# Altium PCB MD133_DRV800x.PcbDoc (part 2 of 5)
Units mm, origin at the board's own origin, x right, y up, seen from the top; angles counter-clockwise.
Board outline 152.66 x 101.89 mm, 4 copper layers (Top Layer, Mid-Layer 1, Mid-Layer 2, Bottom Layer), stack 2.355 mm thick; 306 components, 166 nets, 1010 pads, 1623 vias.
Unrouted connection lines stored in the file: 4.
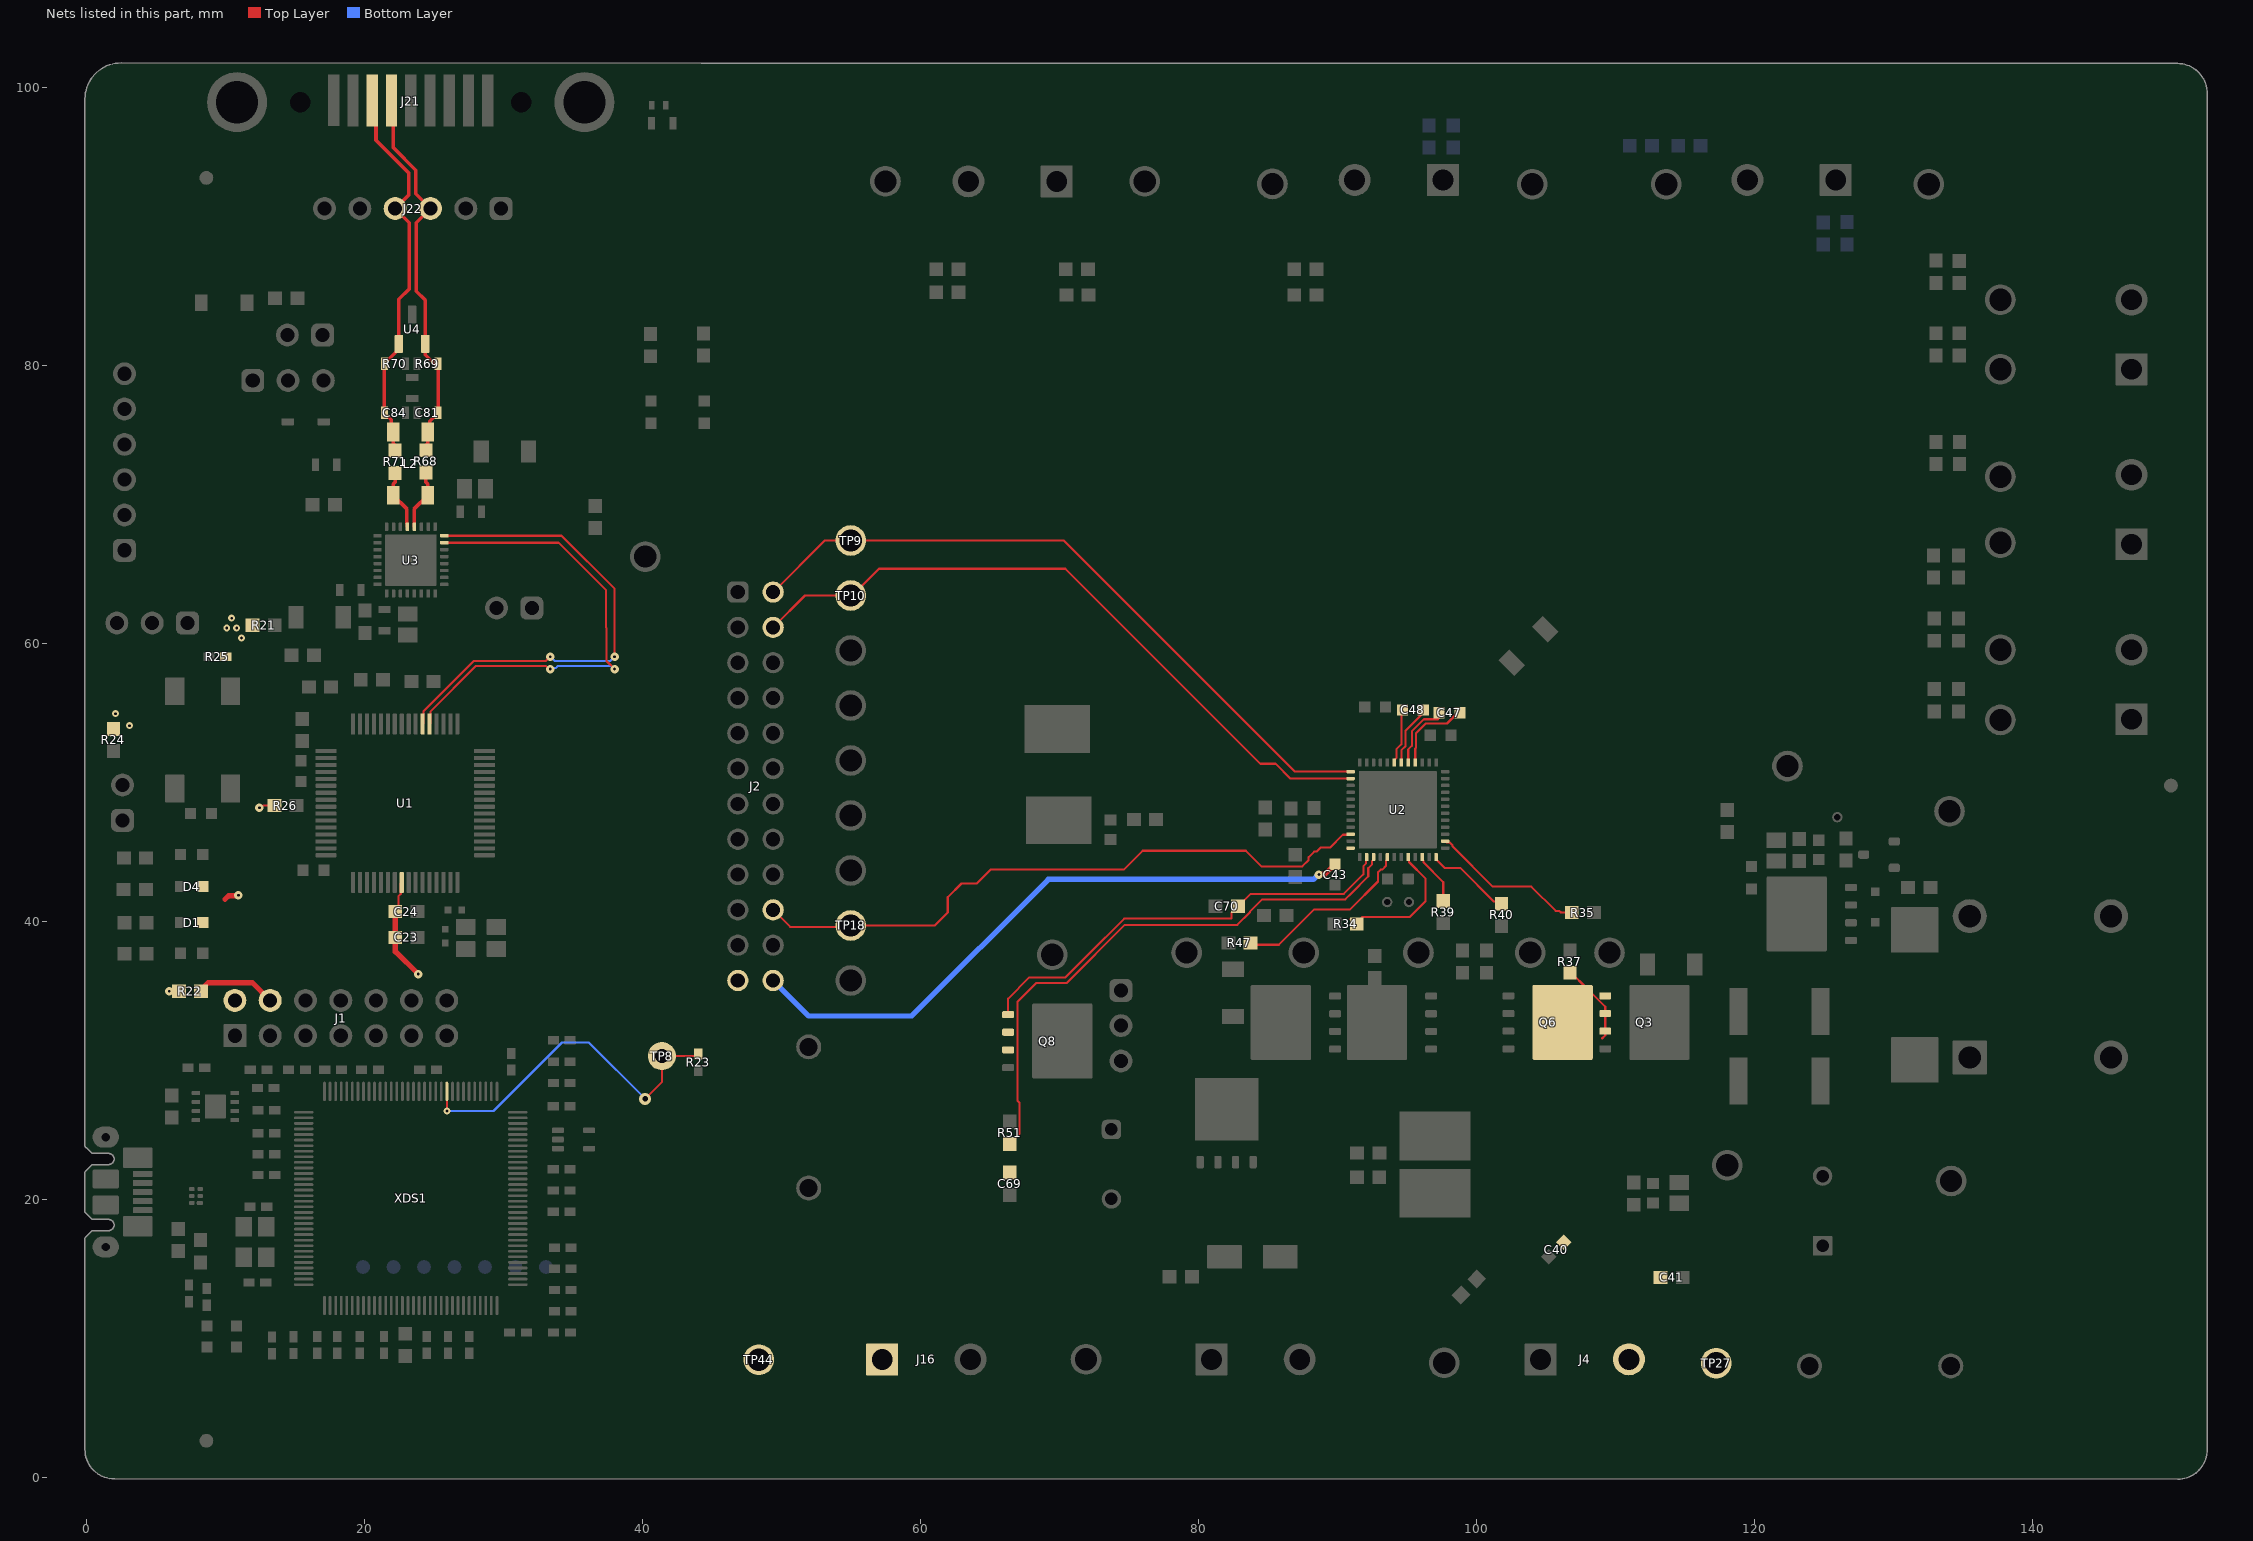
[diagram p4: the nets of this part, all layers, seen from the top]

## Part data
C1 C15: library part CMP-0006906-5, "CAP, CERM, 2.2 uF, 10 V, +/- 10%, X5R, 0603", Cap_Case=0603, Manufacturer=Kemet, Supplier Part Number 1=399-4911-1-ND, TempCo=X5R, Tolerance_%=10%, Value1=Unknown, Value2=10V, ValueDisplayed=2.2uF
C2: library part CMP-0006688-2, "CAP, CERM, 3300 pF, 50 V, +/- 10%, X7R, 0402", Cap_Case=0402, Manufacturer=MuRata, Supplier Part Number 1=490-3248-1-ND, TempCo=X7R, Tolerance_%=10%, Value1=Unknown, Value2=50V, ValueDisplayed=3300pF
C3 C10 C13 C17: library part CMP-0006276-2, "CAP, CERM, 1 uF, 25 V, +/- 10%, X5R, 0402", Cap_Case=0402, Manufacturer=TDK, Supplier Part Number 1=445-9066-1-ND, TempCo=X5R, Tolerance_%=10%, Value1=Unknown, Value2=25V, ValueDisplayed=1uF
C4: library part CMP-0006341-2, "CAP, CERM, 2.2 uF, 6.3 V, +/- 10%, X5R, 0402", Cap_Case=0402, Manufacturer=Samsung, Supplier Part Number 1=1276-1172-1-ND, TempCo=X5R, Tolerance_%=10%, Value1=Unknown, Value2=6.3V, ValueDisplayed=2.2uF
C5 C6 C7 C14 C20: library part CMP-0006658-2, "CAP, CERM, 0.01 uF, 25 V, +/- 10%, X7R, 0402", Cap_Case=0402, Manufacturer=MuRata, Supplier Part Number 1=490-1312-1-ND, TempCo=X7R, Tolerance_%=10%, Value1=Unknown, Value2=25V, ValueDisplayed=0.01uF
C8 C9 C11 C12 C16 C21 C22: library part CMP-0006623-2, "CAP, CERM, 0.1 uF, 6.3 V, +/- 10%, X7R, 0402", Cap_Case=0402, Manufacturer=MuRata, Supplier Part Number 1=GRM155R70J104KA01D-ND, TempCo=X7R, Tolerance_%=10%, Value1=Unknown, Value2=6.3V, ValueDisplayed=0.1uF
C18 C19: library part CMP-0006415-2, "CAP, CERM, 12 pF, 50 V, +/- 5%, C0G/NP0, 0402", Cap_Case=0402, Manufacturer=MuRata, Supplier Part Number 1=14T3292, TempCo=C0G/NP0, Tolerance_%=5%, Value1=Unknown, Value2=50V, ValueDisplayed=12pF
C23: library part CMP-0860569-1, "CAP, CERM, 10 µF, 25 V,+/- 10%, X5R, 0603", Cap_Case=0603, Manufacturer=MuRata, TempCo=X5R, Tolerance_%=10%, Value2=25V, ValueDisplayed=10µF
C24 C34 C37 C86: library part CMP-0006837-4, "CAP, CERM, 0.1 uF, 50 V, +/- 10%, X7R, 0603", Cap_Case=0603, Manufacturer="Wurth Elektronik", TempCo=X7R, Tolerance_%=10%, Value1=Unknown, Value2=50V, ValueDisplayed=0.1uF
C25: library part CMP-0119380-1, "WCAP-CSGP Multilayer Ceramic Chip Capacitor, General Purpose, size 0603, X7R Class II, 470nF, 25VDC", Capacitance Tolerance=+/-10%, Case/Size Code=0603, Insulation Resistance=1.1GOhm, Manufacturer="Wurth Elektronik", Operating Temperature Max=125°C, Operating Temperature Min=-55°C, Rated Voltage (DC)=25V
C26: library part CMP-0104705-1, "WCAP-CSGP Multilayer Ceramic Chip Capacitor, General Purpose, size 0603, X7R, 10nF, 25VDC", Capacitance Tolerance=+/-10%, Case/Size Code=0603, Insulation Resistance=10GOhm, Manufacturer="Wurth Elektronik", Operating Temperature Max=125°C, Operating Temperature Min=-55°C, Rated Voltage (DC)=25V
C27: library part CMP-0115494-1, "WCAP-CSGP Multilayer Ceramic Chip Capacitor, General Purpose, size 0603, X7R, 1µF, 50VDC", Capacitance Tolerance=+/-10%, Case/Size Code=0603, Insulation Resistance=0.5GOhm, Manufacturer="Wurth Elektronik", Operating Temperature Max=125°C, Operating Temperature Min=-55°C, Rated Voltage (DC)=50V
C28 C29: library part CMP-0050268-1, "WCAP-CSGP Multilayer Ceramic Chip Capacitor, General Purpose, size 0402, NP0, 22pF, 50VDC", Capacitance Tolerance=+/-5%, Case/Size Code=0402, Insulation Resistance=10GOhm, Manufacturer="Wurth Elektronik", Operating Temperature Max=125°C, Operating Temperature Min=-55°C, Rated Voltage (DC)=50V
C30 C32: library part CMP-0077698-1, "CAP, CERM, 1 µF, 100 V,+/- 10%, X7R, 1206", Cap_Case=1206, Manufacturer="Yageo America", Supplier Part Number 1=311-1948-1-ND, TempCo=X7R, Tolerance_%=10%, Value2=100V, ValueDisplayed=1µF
C31: library part CMP-0105981-1, "WCAP-ATG5 Aluminum Electrolytic Capacitor, Radial, THT, D10 x H12.5mm, 220µF, 50V", Capacitance Tolerance=+/-20%, Leakage Current=110uA, Manufacturer="Wurth Elektronik", Operating Temperature Max=105°C, Operating Temperature Min=-40°C, Rated Voltage (DC)=50V, Ripple Current=345mA
C33 C36: library part CMP-0750039-1, "CAP, CERM, 0.01 µF, 50 V,+/- 10%, X7R, 0603", Cap_Case=0603, Manufacturer="Wurth Elektronik", TempCo=X7R, Tolerance_%=10%, Value2=50V, ValueDisplayed=0.01µF
C35 C38: library part CMP-0007696-2, "CAP, CERM, 1 uF, 50 V, +/- 10%, X7R, 0805", Cap_Case=0805, Manufacturer="Wurth Elektronik", Supplier Part Number 1=710-885012207103, TempCo=X7R, Tolerance_%=10%, Value1=Unknown, Value2=50V, ValueDisplayed=1uF
C39: library part CMP-0087013-2, "Electrolytic Capacitor, 330 uF, 50 V, WCAP-ATG5 Series, 20%, Radial Leaded, 10 mm", Manufacturer="Wurth Electronics", Tolerance_%=20%, ValueDisplayed=330uF
C40 C45 C47 C48: library part CMP-0108322-1, "WCAP-CSGP Multilayer Ceramic Chip Capacitor, General Purpose, size 0603, X7R, 100nF, 100VDC", Capacitance Tolerance=+/-10%, Case/Size Code=0603, Insulation Resistance=1GOhm, Manufacturer="Wurth Elektronik", Operating Temperature Max=125°C, Operating Temperature Min=-55°C, Rated Voltage (DC)=100V
C41 C42 C49 C50 C51 C52 C53 C54 C55 C56 C57 C58 C59 C60 C61 C64 C65 C66 C71 C72 C73 C87 C88 C89 C90 C91 C92: library part CMP-0006836-4, "CAP, CERM, 0.022 uF, 50 V, +/- 10%, X7R, 0603", Cap_Case=0603, Manufacturer="Wurth Elektronik", TempCo=X7R, Tolerance_%=10%, Value1=Unknown, Value2=50V, ValueDisplayed=0.022uF
C43 C46: library part CMP-0108290-1, "WCAP-CSGP Multilayer Ceramic Chip Capacitor, General Purpose, size 0603, X7R, 1µF, 25VDC", Capacitance Tolerance=+/-10%, Case/Size Code=0603, Insulation Resistance=0.5GOhm, Manufacturer="Wurth Elektronik", Operating Temperature Max=125°C, Operating Temperature Min=-55°C, Rated Voltage (DC)=25V
C44: library part CMP-0081454-1, "CAP, CERM, 10 µF, 50 V,+/- 20%, X5R, 1206", Cap_Case=1206, Manufacturer="Wurth Elektronik", TempCo=X5R, Tolerance_%=20%, Value2=50V, ValueDisplayed=10µF
C62: library part CMP-0087155-1, "CAP CER 0.015UF 50V X7R 0603", Manufacturer="Wurth Electronics", TempCo=15%, Tolerance_%=10%
C63: library part CMP-0006828-4, "CAP, CERM, 0.01 uF, 16 V, +/- 10%, X7R, 0603", Cap_Case=0603, Manufacturer="Wurth Elektronik", Supplier Part Number 1=732-7959-1-ND, TempCo=X7R, Tolerance_%=10%, Value1=Unknown, Value2=16V, ValueDisplayed=0.01uF
C67 C69: library part CMP-0080094-1, "CAP, CERM, 5100 pF, 50 V,+/- 5%, C0G/NP0, 0603", Cap_Case=0603, Manufacturer=Kemet, Supplier Part Number 1=399-9975-1-ND, TempCo=C0G/NP0, Tolerance_%=5%, Value2=50V, ValueDisplayed=5100pF
C68: library part CMP-0079993-1, "CAP, CERM, 0.01 µF, 100 V,+/- 10%, X7R, 0603", Cap_Case=0603, Manufacturer="Wurth Elektronik", Supplier Part Number 1=45AC8565, TempCo=X7R, Tolerance_%=10%, Value2=100V, ValueDisplayed=0.01µF
C70: library part CMP-0074687-3, "CAP, CERM, 0.22 µF, 10 V,+/- 10%, X7R, 0603", Cap_Case=0603, Manufacturer="Wurth Elektronik", Supplier Part Number 1=732-7941-1-ND, TempCo=X7R, Tolerance_%=10%, Value2=10V, ValueDisplayed=0.22µF
C74 C77 C79: library part CMP-0007044-5, "CAP, CERM, 0.1 uF, 50 V, +/- 10%, X7R, 0603", Cap_Case=0603, Manufacturer=TDK, Supplier Part Number 1=445-1314-1-ND, TempCo=X7R, Tolerance_%=10%, Value1="0.0296 ohm", Value2=50V, ValueDisplayed=0.1uF
C75 C83: library part CMP-0080701-1, "CAP, CERM, 4.7 µF, 16 V,+/- 10%, X7R, AEC-Q200 Grade 1, 0805", Cap_Case=0805, Manufacturer=TDK, Supplier Part Number 1=445-8788-1-ND, TempCo=X7R, Tolerance_%=10%, Value2=16V, ValueDisplayed=4.7µF
C76 C78: library part CMP-0008802-2, "CAP, CERM, 10 uF, 50 V, +/- 10%, X7R, 1206", Cap_Case=1206, Manufacturer=Samsung, Supplier Part Number 1=1276-6767-1-ND, TempCo=X7R, Tolerance_%=10%, Value1=Unknown, Value2=50V, ValueDisplayed=10uF
C80: library part CMP-0006776-4, "CAP, CERM, 220 pF, 50 V, +/- 1%, C0G/NP0, 0603", Cap_Case=0603, Manufacturer=AVX, Supplier Part Number 1=478-3719-1-ND, TempCo=C0G/NP0, Tolerance_%=1%, Value1="0.083 ohm", Value2=50V, ValueDisplayed=220pF
C81 C84: library part CMP-0007253-4, "CAP, CERM, 20 pF, 100 V, +/- 5%, C0G/NP0, 0603", Cap_Case=0603, Manufacturer=MuRata, Supplier Part Number 1=490-1334-1-ND, TempCo=C0G/NP0, Tolerance_%=5%, Value1=Unknown, Value2=100V, ValueDisplayed=20pF
C82: library part CMP-0006746-5, "CAP, CERM, 4700 pF, 100 V, +/- 10%, X7R, 0603", Cap_Case=0603, Manufacturer=AVX, Supplier Part Number 1=478-1203-1-ND, TempCo=X7R, Tolerance_%=10%, Value1="0.136 ohm", Value2=100V, ValueDisplayed=4700pF
C85: library part CMP-0006977-4, "CAP, CERM, 0.01 uF, 100 V, +/- 10%, X7R, 0603", Cap_Case=0603, Manufacturer=Kemet, Supplier Part Number 1=399-5347-1-ND, TempCo=X7R, Tolerance_%=10%, Value1=Unknown, Value2=100V, ValueDisplayed=0.01uF
D1 D2 D3 D6 D7 D10: library part CMP-0002894-2, "LED, Green, SMD", Color=green, Manufacturer="Wurth Elektronik", Value1=W, Value2=2V
D4: library part CMP-0002947-3, "LED, Red, SMD", Color=Red, Manufacturer="Wurth Elektronik", Power_TotalModule=72mW, Value1=0.072W, Value2=2V
D5: library part CMP-0079597-2, "Diode, Switching, 75 V, 0.15 A, AEC-Q101, SOD-323", Manufacturer="Diodes Inc.", Value1=0.15A, Value2=1.25V
D8: library part CMP-0076974-2, "Diode, Switching, 100 V, 0.15 A, SOD-123", Manufacturer="Micro Commercial Components", Value1=0.15A, Value2=1.25V
D9: library part CMP-0098376-1, "24-V, 1-Channel ESD Protection Diode", Breakdown Voltage=25.5V, Clamping Voltage=40V, Digikey Part Number=296-ESD1LIN24DYFRCT-ND, Manufacturer="Texas Instruments", Mouser Part Number=595-ESD1LIN24DYFR, Operating Temperature Range="-55°C to +150°C", ValueDisplayed=2.3pF
D11: library part CMP-0128434-1, "Rectifier Diode, Schottky, 1 Phase, 1 Element, 3A, 40V V(RRM), Silicon, DO-214AC", Digikey Part Number=B340AE-13DICT-ND, Forward Current=3A, Manufacturer="Diodes Incorporated", Max Surge Forward Current=80A, Mouser Part Number=621-B340AE-13, Operating Temperature Range="-55°C to +150°C", Peak Reverse Current=0.2mA, ValueDisplayed=140pF
F1: library part CMP-0077200-3, "Fuse, 30 A, 250 VAC, 100 VDC, SMD", Irating_A=30A, Manufacturer=Littelfuse, Supplier Part Number 1=F6439CT-ND
FID1 FID2 FID3: library part CMP-0077181-1, "Fiducial mark.  There is nothing to buy or mount.", Manufacturer=N/A
H1 H2 H3 H4: library part CMP-0003620-1, "Bumpon, Hemisphere, 0.44 X 0.20, Clear", Manufacturer=3M, Supplier Part Number 1=SJ5303-7-ND
IC1: library part CMP-0043115-3, "4-Channel ESD Protection Array for High-Speed Data Interfaces, DRY0006A (USON-6)", Breakdown Voltage(Min)(V)=6, IO Capacitance(Typ)(pF)=1.6, IO Leakage Current(nA)=1, Manufacturer="Texas Instruments", Operating Temperature Range="-40 to 85 C", Rating=Catalog
IC2: library part CMP-0036329-3, "500mA, Adjustable, Low Quiescent Current, Low-Noise, High-PSRR, Single-Output LDO Regulator, DRB0008A (VSON-8)", Manufacturer="Texas Instruments", Operating Temperature Range="-40 to 125 C", Rating=Catalog
IC3: library part CMP-0032790-2, "Precision Micropower Shunt Voltage Reference, 0.5% accuracy, 2.5 V, 15 ppm / degC, 15 mA, -40 to 85 degC, 5-pin SC70 (DCK), Green (RoHS & no Sb/Br)", Manufacturer="Texas Instruments", Rating=Catalog, Temp Coeff(Max)(ppm/ degree C)=100, Temp Coeff(Typ)(ppm/ degree C)=15
J1: library part CMP-0075415-2, "Header, 100mil, 7x2, Gold, TH", Color=Black, Current_A=6.3A, Manufacturer=Samtec, Supplier Part Number 1=SAM1028-07-ND, Voltage_V=550V
J2: library part CMP-0750191-1, "Header, 2.54mm, 12x2, Gold, TH", Color=Black, Manufacturer=Samtec, Voltage_V=550V
J3 J18 J20: library part CMP-0075405-3, "Header, 100mil, 2x1, Gold, TH", Color=Black, Current_A=6.3A, Manufacturer=Samtec, Supplier Part Number 1=SAM1029-02-ND, Voltage_V=550V
J4 J6 J7 J8 J9 J16: library part CMP-0093233-2, "2 Position Wire to Board Terminal Block Horizontal with Board 0.250\" (6.35mm) Through Hole", Current_A=32A, Digikey Part Number=732-691250610002-ND, Manufacturer="Wurth Electronics", Mouser Part Number=710-691250610002, Operating Temperature Range="-32°C to +120°C", Voltage_V=450V
J5: library part CMP-0086764-1, "2 Position Wire to Board Terminal Block Horizontal with Board 0.400\" (10.16mm) Through Hole", Current_A=57A, Manufacturer=Wurth, Voltage_V=750V
J10 J11 J12: library part CMP-0096350-1, "2 Position Wire to Board Terminal Block Horizontal with Board 0.197\" (5.00mm) Through Hole", Current_A=14A, Digikey Part Number=732-691216710002-ND, Manufacturer="Wurth Electronics", Mouser Part Number=710-691216710002, Operating Temperature Range="-30°C to +120°C", Voltage_V=300V
J13 J19 J23: library part CMP-0075407-2, "Header, 100mil, 3x1, Gold, TH", Color=Black, Current_A=6.3A, Manufacturer=Samtec, Supplier Part Number 1=SAM1029-03-ND, Voltage_V=550V
J17 J22: library part CMP-0075413-2, "Header, 100mil, 6x1, Gold, TH", Color=Black, Current_A=6.3A, Manufacturer=Samtec, Supplier Part Number 1=SAM1029-06-ND, Voltage_V=550V
J21: library part CMP-0074875-1, "Receptacle, D-Sub, 9 Position, R/A, SMT", Color=Black, Manufacturer=NorComp, Supplier Part Number 1=190-09FA-ND
L1: library part CMP-0087162-1, "FIXED IND 2.2UH 16A 2.2 MOHM", Manufacturer="Wurth Electronics"
L2: library part CMP-0062430-2, "Inductor, Ferrite, 100 uH, 0.15 A, 2 ohm, SMD", Manufacturer=TDK, Supplier Part Number 1=445-3959-1-ND, Value1="2 ohm", Value2=0.15A, ValueDisplayed=100uH
LED1: library part CMP-0078131-2, "LED, Red, SMD", Color=Red, Manufacturer=Lite-On, Power_TotalModule=62.5mW, Value1=.0625W, Value2=2V
LED2: library part CMP-0002827-3, "LED, Green, SMD", Color=green, Manufacturer=Lite-On, Power_TotalModule=100mW, Value1=0.1W, Value2=2.1V
Logo1: library part CMP-0074844-1
Logo2: library part CMP-0074838-1, "Texas Instrument Corporate Signature"
Logo3: library part CMP-0074847-1, "FCC_disclaimer"
Logo4: library part CMP-0074769-3, Manufacturer="Texas Instruments"
LOGO5 LOGO7: library part CMP-0074837-2, "IEC 61010-1 Hot Surface Warning", Manufacturer="Texas Instruments"
Logo6: library part CMP-0074836-1, "IEC 61010-1 Caution Warning"
Q1: library part CMP-0000375-2, "Transistor, NPN, 65 V, 0.1 A, SOT-23", Manufacturer="ON Semiconductor", Supplier Part Number 1=BC846BLT1GOSCT-ND, Value1="0.1 A", Value2=450
Q2 Q3 Q4 Q5 Q6 Q8: library part CMP-0000713-2, "MOSFET, N-CH, 40 V, 100 A, DNK0008A (VSON-CLIP-8)", Alternate Manufacturer=None, Manufacturer="Texas Instruments", Supplier Part Number 1=CSD18512Q5B-ND, Value1=0.002, Value2="37 nC"
Q7: library part CMP-0000594-1, "MOSFET, N-CH, 30 V, 25 A, DQJ0008A (VSONP-8)", Alternate Manufacturer=None, Manufacturer="Texas Instruments", Supplier Part Number 1=CSD17579Q5A-ND, Value1=0.013, Value2="11.6 nC"
R1: library part CMP-0026731-1, "RES, 330 k, 1%, 0.0625 W, 0402", Manufacturer="Yageo America", Power_W=62.5mW, Supplier Part Number 1=311-330KLRCT-ND, TempCo="100 ppm/C", Tolerance_%=1%, Value2=0.0625W, Value_Code=330k
R2 R5 R52 R58 R68 R71: library part CMP-0025885-5, "RES, 0, 5%, 0.1 W, 0603", Manufacturer=Yageo, Power_W=100mW, Supplier Part Number 1=311-0.0GRCT-ND, TempCo="200 ppm/C", Tolerance_%=5%, Value2=0.1W, Value_Code=0000, ValueDisplayed=0
R3: library part CMP-0026728-1, "RES, 220 k, 1%, 0.0625 W, 0402", Manufacturer="Yageo America", Power_W=62.5mW, Supplier Part Number 1=311-220KLRCT-ND, TempCo="100 ppm/C", Tolerance_%=1%, Value2=0.0625W, Value_Code=220k
R4: library part CMP-0026695-1, "RES, 3.30 k, 1%, 0.1 W, AEC-Q200 Grade 0, 0402", Manufacturer=Panasonic, Power_W=100mW, Supplier Part Number 1=P3.30KLCT-ND, TempCo="100 ppm/C", Tolerance_%=1%, Value2=0.1W, Value_Code=3k30, ValueDisplayed=3.30k
R6: library part CMP-0026100-2, "RES, 1.00 M, 1%, 0.063 W, AEC-Q200 Grade 0, 0402", Manufacturer=Vishay-Dale, Power_W=63mW, Supplier Part Number 1=541-1.00MLCT-ND, TempCo="100 ppm/C", Tolerance_%=1%, Value2=0.063W, Value_Code=1M00, ValueDisplayed=1.00M
R7 R8 R14: library part CMP-0026825-5, "RES, 10 k, 5%, 0.063 W, AEC-Q200 Grade 0, 0402", Manufacturer=Vishay-Dale, Power_W=63mW, Supplier Part Number 1=541-10KJCT-ND, TempCo="200 ppm/C", Tolerance_%=5%, Value2=0.063W, Value_Code=10k0, ValueDisplayed=10k
R9 R10 R11 R12 R17: library part CMP-0026852-3, "RES, 1.0 k, 5%, 0.063 W, AEC-Q200 Grade 0, 0402", Manufacturer=Vishay-Dale, Power_W=63mW, Supplier Part Number 1=541-1.0KJCT-ND, TempCo="200 ppm/C", Tolerance_%=5%, Value2=0.063W, Value_Code=1k00, ValueDisplayed=1.0k
R13 R16: library part CMP-0026824-3, "RES, 100, 5%, 0.063 W, AEC-Q200 Grade 0, 0402", Manufacturer=Vishay-Dale, Power_W=63mW, Supplier Part Number 1=541-100JCT-ND, TempCo="200 ppm/C", Tolerance_%=5%, Value2=0.063W, Value_Code=100R, ValueDisplayed=100
R15: library part CMP-0026413-2, "RES, 4.87 k, 1%, 0.063 W, AEC-Q200 Grade 0, 0402", Manufacturer=Vishay-Dale, Power_W=63mW, Supplier Part Number 1=541-4.87KLCT-ND, TempCo="100 ppm/C", Tolerance_%=1%, Value2=0.063W, Value_Code=4k87, ValueDisplayed=4.87k
R18: library part CMP-0026946-3, "RES, 51, 5%, 0.063 W, AEC-Q200 Grade 0, 0402", Manufacturer=Vishay-Dale, Power_W=63mW, Supplier Part Number 1=541-51JCT-ND, TempCo="200 ppm/C", Tolerance_%=5%, Value2=0.063W, Value_Code=51R0, ValueDisplayed=51
R19 R20: library part CMP-0026934-3, "RES, 470, 5%, 0.063 W, AEC-Q200 Grade 0, 0402", Manufacturer=Vishay-Dale, Power_W=63mW, Supplier Part Number 1=541-470JCT-ND, TempCo="200 ppm/C", Tolerance_%=5%, Value2=0.063W, Value_Code=470R, ValueDisplayed=470
R21 R22 R26 R27 R34 R35 R37 R38 R39 R40 R41 R42 R45 R53 R64: library part CMP-0025885-5, "RES, 0, 5%, 0.1 W, 0603", Manufacturer=Yageo, PartNumber=RC0603JR-070RL, Power_W=100mW, Supplier Part Number 1=311-0.0GRCT-ND, TempCo="200 ppm/C", Tolerance_%=5%, Value2=0.1W, Value_Code=0000, ValueDisplayed=0
R23 R25: library part CMP-0026935-3, "RES, 47 k, 5%, 0.063 W, AEC-Q200 Grade 0, 0402", Manufacturer=Vishay-Dale, Power_W=63mW, Supplier Part Number 1=541-47KJCT-ND, TempCo="200 ppm/C", Tolerance_%=5%, Value2=0.063W, Value_Code=47k0, ValueDisplayed=47k
R24 R43 R73 R74: library part CMP-0025918-5, "RES, 3.3 k, 5%, 0.1 W, 0603", Manufacturer=Yageo, Power_W=100mW, Supplier Part Number 1=311-3.3KGRCT-ND, TempCo="100 ppm/C", Tolerance_%=5%, Value2=0.1W, Value_Code=3k30, ValueDisplayed=3.3k
R28 R29 R30 R31 R63: library part CMP-0025912-5, "RES, 330, 5%, 0.1 W, 0603", Manufacturer=Yageo, Power_W=100mW, Supplier Part Number 1=311-330GRCT-ND, TempCo="100 ppm/C", Tolerance_%=5%, Value2=0.1W, Value_Code=330R, ValueDisplayed=330
R32 R33 R67: library part CMP-0025886-5, "RES, 10 k, 5%, 0.1 W, 0603", Manufacturer=Yageo, Power_W=100mW, Supplier Part Number 1=311-10KGRCT-ND, TempCo="100 ppm/C", Tolerance_%=5%, Value2=0.1W, Value_Code=10k0, ValueDisplayed=10k
R36: library part CMP-0086254-1, "RES, 0.007, 1%, 7 W, AEC-Q200 Grade 0, 7.1x4.6mm", Manufacturer=Vishay-Dale, Power_W=7W, TempCo="75 ppm/C", Tolerance_%=1%, Value_Code=7L000, ValueDisplayed=0.007
R44: library part CMP-0025891-5, "RES, 16 k, 5%, 0.1 W, 0603", Manufacturer=Yageo, Power_W=100mW, Supplier Part Number 1=311-16KGRCT-ND, TempCo="100 ppm/C", Tolerance_%=5%, Value2=0.1W, Value_Code=16k0, ValueDisplayed=16k
R47 R65: library part CMP-0025899-5, "RES, 1.0 k, 5%, 0.1 W, 0603", Manufacturer=Yageo, Power_W=100mW, Supplier Part Number 1=311-1.0KGRCT-ND, TempCo="100 ppm/C", Tolerance_%=5%, Value2=0.1W, Value_Code=1k00, ValueDisplayed=1.0k
R51: library part CMP-0022918-5, "RES, 220, 1%, 0.1 W, 0603", Manufacturer=Yageo, Power_W=100mW, Supplier Part Number 1=311-220HRCT-ND, TempCo="100 ppm/C", Tolerance_%=1%, Value2=0.1W, Value_Code=220R, ValueDisplayed=220
R57: library part CMP-0022895-5, "RES, 1.00 k, 1%, 0.1 W, 0603", Manufacturer=Yageo, Power_W=100mW, Supplier Part Number 1=311-1.00KHRCT-ND, TempCo="100 ppm/C", Tolerance_%=1%, Value2=0.1W, Value_Code=1k00, ValueDisplayed=1.00k
R62: library part CMP-0025930-5, "RES, 560, 5%, 0.1 W, 0603", Manufacturer=Yageo, Power_W=100mW, Supplier Part Number 1=311-560GRCT-ND, TempCo="100 ppm/C", Tolerance_%=5%, Value2=0.1W, Value_Code=560R, ValueDisplayed=560
R66 R75: library part CMP-0078790-1, "RES, 0, 0.05%, 2 W, AEC-Q200 Grade 0, 2512", Manufacturer="Stackpole Electronics Inc", Power_W=2W, Supplier Part Number 1=HCJ2512ZT0R00CT-ND, Tolerance_%=0.05%, Value_Code=0
R69 R70: library part CMP-0023213-5, "RES, 60.4, 1%, 0.1 W, 0603", Manufacturer=Yageo, Power_W=100mW, Supplier Part Number 1=311-60.4HRCT-ND, TempCo="100 ppm/C", Tolerance_%=1%, Value2=0.1W, Value_Code=60R4, ValueDisplayed=60.4
R72: library part CMP-0026660-1, "RES, 1.00 M, 1%, 0.1 W, 0402", Manufacturer=Panasonic, Power_W=100mW, Supplier Part Number 1=P1.00MLCT-ND, TempCo="100 ppm/C", Tolerance_%=1%, Value2=0.1W, Value_Code=1M00, ValueDisplayed=1.00M
R76: library part CMP-0025900-5, "RES, 20 k, 5%, 0.1 W, 0603", Manufacturer=Yageo, Power_W=100mW, Supplier Part Number 1=311-20KGRCT-ND, TempCo="100 ppm/C", Tolerance_%=5%, Value2=0.1W, Value_Code=20k0, ValueDisplayed=20k
R77: library part CMP-0025898-5, "RES, 1.8 k, 5%, 0.1 W, 0603", Manufacturer=Yageo, Power_W=100mW, Supplier Part Number 1=311-1.8KGRCT-ND, TempCo="100 ppm/C", Tolerance_%=5%, Value2=0.1W, Value_Code=1k80, ValueDisplayed=1.8k
S1: library part CMP-0097347-1, "Tactile Switch SPST-NO Top Actuated Surface Mount", Coil Resistance_ohm=100mΩ, Contact Current Rating=50mA, Digikey Part Number=732-7022-1-ND, Manufacturer="Wurth Electronics", Mouser Part Number=710-430481025816, Operating Force=160gf, Operating Temperature Range="-40°C to +85°C"
SH1 SH2: library part CMP-0075110-1, "1mm Uninsulated Shorting Plug, 10.16mm spacing, TH", Manufacturer=Harwin, PartNumber=D3082-05, Supplier Part Number 1=952-1873-ND
SH-J1 SH-J2 SH-J3 SH-J4 SH-J5 SH-J6 SH-J7 SH-J8 SH-J9 SH-J10 SH-J11 SH-J12 SH-J13 SH-J14 SH-J15 SH-J16 SH-J17 SH-J18 SH-J19 SH-J20 SH-J21: library part CMP-0003761-2, "Shunt, 2.54mm, Gold, Black", Manufacturer="Wurth Elektronik", Supplier Part Number 1=732-2678-ND
TP1 TP2 TP3 TP4 TP5 TP6 TP7: library part CMP-0003825-1, "1mm Test Point, SMT", Manufacturer=Any, PartNumber=TP_SM_1MM
TP8: library part CMP-0055139-2, "Test Point, Miniature, White, TH", Color=White, Manufacturer="Keystone Electronics", Supplier Part Number 1=36-5002-ND
TP9 TP10 TP11 TP12 TP13 TP14 TP15 TP18 TP19 TP22 TP23 TP24 TP27 TP28 TP29 TP31 TP32 TP33 TP34 TP35 TP36 TP37 TP38 TP39 TP40 TP41 TP42 TP44 TP46 TP47 TP48 TP49: library part CMP-0055149-2, "Test Point, Multipurpose, White, TH", Color=White, Manufacturer="Keystone Electronics", Supplier Part Number 1=36-5012-ND
TP16 TP17: library part CMP-0055153-2, "Test Point, Compact, SMT", Manufacturer="Keystone Electronics", Supplier Part Number 1=36-5016TR-ND
TP20 TP21: library part CMP-0055147-2, "Test Point, Multipurpose, Red, TH", Color=Red, Manufacturer="Keystone Electronics", Supplier Part Number 1=36-5010-ND
TP25 TP26: library part CMP-0055148-2, "Test Point, Multipurpose, Black, TH", Color=Black, Manufacturer="Keystone Electronics", Supplier Part Number 1=36-5011-ND
TP30 TP43 TP45: library part CMP-0003719-1, "Testpoint", Manufacturer="Texas Instruments"
U1: library part CMP-0093960-1, "Mixed-Signal Microcontrollers With CAN-FD Interface LQFP64", Frequency_Fixed=80MHz, Manufacturer="Texas Instruments", Max Supply Voltage=3.6V, Min Supply Voltage=1.62V, Operating Temperature Range="-40°C to +125°C"
U2: library part CMP-0128166-1, Manufacturer="Texas Instruments", Operating Temperature Range=to
U3: library part CMP-0093295-1, "CAN FD and LIN System Basis Chip (SBC) with Integrated Watchdog, Selective Wake and Advanced CAN Bus Fault Diagnostics", Manufacturer="Texas Instruments", Max Supply Voltage=28V, Min Supply Voltage=4.5V, Operating Temperature Range="-40°C to +150°C"
U4: library part CMP-0093261-1, "24-V, 2-Channel ESD Protection Diode for In-Vehicle Networks", Breakdown Voltage=25.5V, Clamping Voltage=32V, Manufacturer="Texas Instruments", Operating Temperature Range="-55°C to +150°C", ValueDisplayed=3pF
USB1: library part CMP-0055311-1, "Receptacle, USB 2.0, Micro B, 5 Position, R/A, SMT", Color=Black, Current_A=1.8A, Manufacturer=Molex, Supplier Part Number 1=WM11263CT-ND, Voltage_V=30V
XDS1: library part CMP-0077954-1, "MSP432E401YTPDT, PDT0128A (TQFP-128)", Alternate Manufacturer="Texas Instruments", Alternate PartNumber=MSP432E401YTPDT
Y1: library part CMP-0004635-3, "Crystal, 16 MHz, 8pF, SMD", Frequency Stability=+/-30ppm, Frequency_Fixed=16MHz, Manufacturer=NDK, Supplier Part Number 1=644-1157-1-ND
Y2: library part CMP-0098168-2, "Crystal 40MHz ±10ppm (Tol) ±20ppm (Stability) 12pF FUND 40Ohm 4-Pin Mini-CSMD T/R", Frequency Stability=20ppm, Frequency Tolerance=10ppm, Frequency_Fixed=40MHz, Load Capacitance=12pF, Manufacturer="Seiko Epson", Operating Temperature Range="-40°C to +105°C"
ZZ1: library part CMP-0003616-3
ZZ2: library part CMP-0077236-1
ZZ3: library part CMP-0077237-1
ZZ4: library part CMP-0077238-1

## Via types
v1: diameter 0.5, hole 0.2, Top Layer to Bottom Layer, tented both sides, 1483 vias
v2: diameter 0.61, hole 0.2, Top Layer to Bottom Layer, tented both sides, 58 vias
v3: diameter 0.508, hole 0.203, Top Layer to Bottom Layer, tented both sides, 46 vias
v4: diameter 0.5, hole 0.2, Top Layer to Bottom Layer, 16 vias
v5: diameter 0.711, hole 0.356, Top Layer to Bottom Layer, tented both sides, 10 vias
v6: diameter 0.61, hole 0.203, Top Layer to Bottom Layer, tented both sides, 5 vias
v7: diameter 5, hole 4.3, Top Layer to Bottom Layer, 3 vias
v8: diameter 5, hole 4.5, Top Layer to Bottom Layer, 1 vias
v9: diameter 0.864, hole 0.406, Top Layer to Bottom Layer, tented both sides, 1 vias

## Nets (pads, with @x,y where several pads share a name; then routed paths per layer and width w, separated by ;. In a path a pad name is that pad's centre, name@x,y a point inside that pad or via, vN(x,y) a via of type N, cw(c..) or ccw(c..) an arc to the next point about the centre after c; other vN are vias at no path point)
3V3: J1.4 R22.1 | length 5.9
  Top Layer w0.381: R22.1@8.13,34.992 8.13,35.017 8.339,35.227 8.364,35.227 8.737,35.6 11.928,35.6 J1.4@13.198,34.33
3V3_MCU: C23.1 C24.1 D1.2 D4.2 J2.23 R21.1 R22.2 R24.2 R25.2 R26.1 U1.40 | length 10.6
  Top Layer w0.152: v2(12.427,48.188) 12.55,48.188 12.701,48.339 R26.1@13.596,48.339 ; C24.1@22.195,40.714 22.418,40.937 22.418,41.809 22.588,41.979 22.588,42.051 22.588,42.74 U1.40@22.662,42.814
  Top Layer w0.381: v2(5.945,34.992) R22.2@6.73,34.992 ; 9.953,41.605 10.194,41.846 10.868,41.846 v2(10.912,41.889) ; C24.1@22.195,40.714 C23.1@22.195,38.862 22.195,37.816 22.257,37.816 v2(23.847,36.226)
  other v1: 3.081,54.089 2.075,54.954 11.142,60.397 10.075,61.108 10.787,61.108 10.431,61.82
+5V: J1.2
BSL_INVOKE: R23.2 TP8.1 XDS1.42 | length 25.6
  Top Layer w0.152: XDS1.42@25.907,27.78 25.907,26.389 v1(25.924,26.372) ; v9(40.177,27.246) 41.377,28.446 TP8.1@41.377,30.328 43.82,30.328 R23.2@43.979,30.486
  Bottom Layer w0.152: v1(25.924,26.372) 29.258,26.372 34.19,31.304 36.12,31.304 v9(40.177,27.246)
CAN_RX: U1.6 U3.24 | length 35.3
  Top Layer w0.152: U1.6@24.162,54.214 24.236,54.288 24.236,55.148 27.835,58.747 33.027,58.747 33.335,59.055 v2(33.345,59.055) ; U3.24@25.72,67.753 34.155,67.753 37.972,63.936 v2(37.972,59.055)
  Bottom Layer w0.152: v2(33.345,59.055) 33.355,59.055 33.663,58.747 37.654,58.747 37.962,59.055 v2(37.972,59.055)
CAN_TX: U1.5 U3.23 | length 34.8
  Top Layer w0.152: U1.5@24.662,54.214 24.736,54.288 24.736,55.123 28.007,58.395 33.027,58.395 33.255,58.166 v2(33.345,58.166) ; U3.23@25.72,67.253 33.948,67.253 37.341,63.86 37.341,61.161 37.391,61.11 37.391,58.747 v2(37.972,58.166)
  Bottom Layer w0.152: v2(33.345,58.166) 33.408,58.229 33.731,58.229 33.897,58.395 37.654,58.395 37.883,58.166 v2(37.972,58.166)
CANH: L2.3 R68.1 U3.28 | length 4.4
  Top Layer w0.254: U3.28@23.57,68.403 23.57,68.83 23.545,68.855 23.545,69.673 24.541,70.669 24.541,71.471 24.398,71.615 R68.1@24.398,72.342
CANH_BUS: C81.1 J21.7 J22.3 L2.2 R68.2 R69.2 U4.2 | length 27.7
  Top Layer w0.254: J21.7@22.066,99.033 22.066,95.663 23.673,94.056 23.673,92.344 J22.3@24.729,91.288 23.713,90.272 23.713,85.349 24.356,84.705 U4.2@24.356,81.558 24.356,80.781 25.275,79.862 C81.1@25.275,76.608 24.668,76.001 24.668,75.346 24.541,75.219 24.541,74.417 24.398,74.274 R68.2@24.398,73.866
CANL: L2.4 R71.1 U3.29 | length 4.4
  Top Layer w0.254: R71.1@22.185,72.318 22.185,71.615 22.041,71.471 22.041,70.669 23.037,69.673 23.037,68.644 23.062,68.619 U3.29@23.062,68.403
CANL_BUS: C84.2 J21.2 J22.4 L2.1 R70.1 R71.2 U4.1 | length 28.1
  Top Layer w0.254: J21.2@20.682,99.033 20.809,98.906 20.809,96.202 23.165,93.846 23.165,92.263 J22.4@22.189,91.288 23.205,90.272 23.205,85.501 22.456,84.752 U4.1@22.456,81.558 22.329,81.431 22.329,81.048 R70.1@21.407,80.125 C84.2@21.407,76.608 21.914,76.1 21.914,75.346 22.041,75.219 22.041,74.417 22.185,74.274 R71.2@22.185,73.842
CP1H: C47.2 U2.4 | length 6
  Top Layer w0.152: U2.4@95.565,51.439 95.565,52.452 95.626,52.512 95.626,53.557 96.316,54.248 97.846,54.248 C47.2@98.78,55.181
CP1L: C47.1 U2.5 | length 5.2
  Top Layer w0.152: U2.5@95.065,51.439 95.065,52.383 95.321,52.639 95.321,53.683 96.19,54.552 97.191,54.552 97.28,54.642 C47.1@97.28,55.181
CP2H: C48.2 U2.6 | length 4.5
  Top Layer w0.152: U2.6@94.565,51.439 94.565,52.314 94.87,52.619 94.87,53.736 C48.2@96.315,55.181
CP2L: C48.1 U2.7 | length 4
  Top Layer w0.152: U2.7@94.065,51.439 94.065,51.614 94.114,51.663 94.122,51.663 94.211,51.752 94.211,52.391 94.565,52.745 C48.1@94.565,54.889 ; C48.1@94.565,54.931 94.64,55.006 C48.1@94.64,55.223
DRVOFF: J2.20 TP18.1 U2.22 | length 46.5
  Top Layer w0.152: J2.20@49.378,40.841 50.604,39.614 54.855,39.614 TP18.1@54.958,39.717 60.999,39.717 61.935,40.653 61.935,41.747 62.929,42.741 64.023,42.741 65.017,43.735 74.593,43.735 75.954,45.095 83.378,45.095 84.5,43.973 87.438,43.973 87.896,44.431 87.896,44.623 88.3,45.027 88.465,45.027 88.769,45.331 89.455,45.331 90.364,46.24 90.866,46.24 U2.22@90.915,46.289
DVDD: C43.2 J2.24 U2.24 | length 46.2
  Top Layer w0.152: U2.24@90.691,45.24 90.74,45.289 U2.24@90.915,45.289
  Top Layer w0.381: v2(88.633,43.376) 88.657,43.4 89.074,43.4 C43.2@89.798,44.123
  Bottom Layer w0.381: J2.24@49.378,35.761 51.934,33.204 59.338,33.204 69.173,43.039 88.235,43.039 88.572,43.376 v2(88.633,43.376)
ECDRV: C69.1 R51.1 U2.27 | length 41.1
  Top Layer w0.152: R51.1@66.391,24.012 66.391,24.037 67.095,24.741 67.095,26.968 66.966,27.096 66.966,34.249 68.299,35.582 70.502,35.582 74.678,39.758 82.761,39.758 83.692,40.689 83.692,40.734 84.553,41.595 90.53,41.595 90.977,42.041 92.184,43.249 92.184,43.835 92.466,44.117 92.466,44.365 92.565,44.464 U2.27@92.565,44.639
ECFB: C70.1 J16.1 Q8.1 Q8.2 Q8.3 TP44.1 U2.26 | length 32
  Top Layer w0.152: Q8.1@66.28,33.309 66.28,34.458 67.808,35.986 70.405,35.986 71.973,37.554 74.629,40.21 82.336,40.21 82.336,40.631 82.383,40.678 82.383,40.703 82.782,41.102 C70.1@82.807,41.102 82.832,41.102 83.725,41.995 90.432,41.995 91.832,43.395 91.832,43.981 92.016,44.165 92.016,44.59 U2.26@92.065,44.639
GD_IN1: J2.2 TP9.1 U2.13 | length 50
  Top Layer w0.152: J2.2@49.378,63.701 53.087,67.41 TP9.1@54.958,67.41 70.273,67.41 86.894,50.789 U2.13@90.915,50.789
GD_IN2: J2.4 TP10.1 U2.14 | length 49.5
  Top Layer w0.152: J2.4@49.378,61.161 51.671,63.454 TP10.1@54.958,63.454 ; TP10.1@55.012,63.4 56.992,65.38 70.398,65.38 84.426,51.351 85.522,51.351 86.585,50.289 U2.14@90.915,50.289
GD_OUT1: C40.2 C41.2 J4.2 Q3.1 Q3.2 Q3.3 Q6.5 Q6.6 Q6.7 Q6.8 Q6.9@106.167,32.75 R37.1 TP27.1 | length 6
  Top Layer w0.152: R37.1@106.689,36.415 107.996,35.108 108.266,34.838 109.234,33.869 Q3.2@109.234,33.385 Q3.3@109.234,32.115 109.234,31.819 109.004,31.589
GH1: R35.2 U2.38 | length 11.4
  Top Layer w0.152: U2.38@97.715,45.789 97.809,45.695 98.028,45.695 98.244,45.479 98.244,45.416 101.147,42.512 103.921,42.512 105.666,40.767 105.937,40.767 106.055,40.648 R35.2@106.925,40.648
GH2: R34.2 U2.32 | length 9.5
  Top Layer w0.152: R34.2@90.908,40.152 R34.2@90.908,40.177 ; R34.2@91.259,39.828 91.259,39.853 91.583,40.177 91.608,40.177 91.759,40.328 95.161,40.328 96.31,41.477 96.31,43.087 95.114,44.283 95.114,44.59 U2.32@95.065,44.639 U2.32@95.114,44.59
GH_HS: R47.2 U2.29 | length 13.3
  Top Layer w0.152: R47.2@83.52,38.333 85.757,38.333 88.303,40.879 90.885,40.879 92.889,42.883 92.889,43.543 93.081,43.735 93.183,43.735 93.466,44.018 93.466,44.326 93.466,44.365 93.565,44.464 U2.29@93.565,44.639
GL1: R40.2 U2.36 | length 6.2
  Top Layer w0.152: U2.36@97.065,44.639 97.065,44.464 97.67,43.859 98.795,43.859 101.208,41.445 101.51,41.445 R40.2@101.773,41.183
GL2: R39.2 U2.34 | length 3.8
  Top Layer w0.152: U2.34@96.065,44.639 96.065,44.464 96.164,44.365 96.164,44.254 97.583,42.834 R39.2@97.583,41.477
